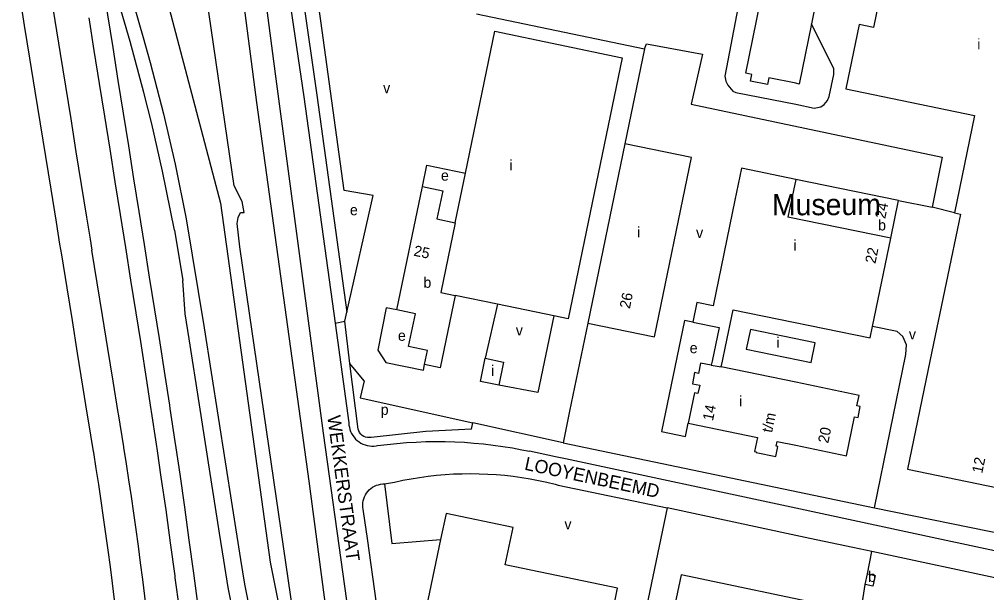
# Model space of a CAD drawing. Extents: x 157699 to 159683, y 381451 to 383293.
# Drawn here: x 157757.7 to 158121.9, y 382412.9 to 382628.7 of the extents above; entities that cross this region are included whole.
import ezdxf

# ---------------------------------------------------------------- set-up
doc = ezdxf.new("R2010")
doc.units = 0
for name, color, linetype in [('BLT_Basislijn', 7, 'Continuous'), ('BLT_Bebouwing', 7, 'Continuous'), ('BLT_Bebouwing_beschrifting', 7, 'Continuous'), ('BLT_Centroide', 7, 'Continuous'), ('BLT_Huisnummer', 7, 'Continuous'), ('BLT_Huisnummer_reeks', 7, 'Continuous'), ('BLT_Onderdoorgang_en_onderverdeling', 7, 'Continuous'), ('BLT_Onderverdeling_panden', 7, 'Continuous'), ('BLT_Straatnaam', 7, 'Continuous'), ('BLT_Vlakafsluiter', 7, 'Continuous')]:
    doc.layers.add(name, color=color, linetype=linetype)

msp = doc.modelspace()

# ---------------------------------------------------------------- linework, layer by layer
at = {"layer": 'BLT_Basislijn'}
for p, q in [((157845.48, 382672.76), (157853.96, 382608.2)), ((157840.85, 382644.96), (157847.02, 382597.39)), ((157857.82, 382647.47), (157864.76, 382599.52)), ((157863.31, 382644.46), (157869.71, 382600.22)), ((157871.21, 382628.11), (157869.03, 382643.28)), ((157929.77, 382630.74), (157993.12, 382617.66)), ((157993.12, 382617.66), (157985.72, 382581.9)), ((157853.96, 382608.2), (157872.09, 382472.97)), ((157847.02, 382597.39), (157866.68, 382454.83)), ((157864.76, 382599.52), (157876.54, 382514.37)), ((157869.71, 382600.22), (157881.02, 382518.43)), ((158088.7, 382560.53), (158101.42, 382557.97)), ((157937.68, 382521.51), (157933.14, 382501.1)), ((157876.54, 382514.37), (157881.73, 382476.82)), ((157882.18, 382499.13), (157880.28, 382515.11)), ((157971.78, 382514.34), (157964.88, 382481.2)), ((157885.29, 382474.45), (157882.18, 382499.13)), ((157887.46, 382492.69), (157882.18, 382499.13)), ((157887.46, 382492.69), (157886.04, 382486.18)), ((157886.04, 382486.18), (157928.38, 382476.87)), ((157964.88, 382481.2), (157962.41, 382469.24)), ((157927.92, 382474.42), (157928.38, 382476.87)), ((157962.41, 382469.24), (157928.38, 382476.87)), ((157910.79, 382473.51), (157890.1, 382471.35)), ((157927.92, 382474.42), (157910.79, 382473.51)), ((157872.09, 382472.97), (157882.28, 382400.27)), ((157959.59, 382464), (157949.82, 382466.12)), ((157962.41, 382469.24), (158079.72, 382444.87)), ((157963.3, 382463.21), (157959.59, 382464)), ((158050, 382444.69), (157963.3, 382463.21)), ((157866.68, 382454.83), (157876.58, 382380.56)), ((157960.62, 382453.39), (158001.58, 382444.81)), ((158001.58, 382444.81), (157980.31, 382343.07)), ((158050, 382434.46), (158001.58, 382444.81)), ((158079.72, 382444.87), (158141.73, 382432.11)), ((158078.71, 382428.33), (158071.51, 382429.87)), ((158167.06, 382409.46), (158078.71, 382428.33)), ((158072.5, 382391.84), (158076.17, 382415.97))]:
    msp.add_line(p, q, dxfattribs=at)
for points in [[(158050, 382728.84), (158049.04, 382728.04), (158047.57, 382725.13), (158047.35, 382722.9), (158028.29, 382633.59), (158023.36, 382607.28), (158023.67, 382605.44), (158024.49, 382603.94), (158026.38, 382601.73), (158027.5, 382601.2), (158050, 382596.73)], [(157814.31, 382688.66), (157806.99, 382684.84), (157802.17, 382680.96), (157802.03, 382678.58), (157833.39, 382559.57), (157852.12, 382424.4), (157856.21, 382403.71), (157863.37, 382370.92), (157866.2, 382371.54)], [(157866.2, 382371.54), (157863.56, 382386.33), (157840.74, 382543.08), (157839.7, 382551.81), (157840.08, 382554.13), (157840.98, 382555.96), (157842.28, 382555.94), (157841.59, 382560.09), (157838.61, 382565.98), (157821.37, 382684.05), (157819.38, 382686.74), (157815.85, 382688.1), (157814.31, 382688.66)], [(157786.93, 382685.77), (157790.71, 382670.14), (157793.44, 382659.75), (157795.78, 382651.33), (157798.88, 382640.71), (157804.35, 382621.87), (157806.97, 382612.47), (157811.94, 382593.14), (157816.3, 382574.16), (157820.46, 382553.59), (157827.25, 382512.59), (157837.82, 382445.33), (157840.91, 382425.36), (157842.49, 382416.11), (157844.46, 382406.06)], [(157814.33, 382483.41), (157812.61, 382494.6), (157810.67, 382506.97), (157810.41, 382508.58), (157808.7, 382519.32), (157806.73, 382531.66), (157804.76, 382544), (157802.79, 382556.35), (157800.82, 382568.69), (157798.85, 382581.04), (157796.88, 382593.38), (157794.91, 382605.72), (157792.94, 382618.07), (157790.97, 382630.41), (157789.01, 382642.76), (157787.04, 382655.1), (157785.07, 382667.44), (157783.19, 382679.23)], [(157816.09, 382549.38), (157811.54, 382571.58), (157807.5, 382589.41), (157804.61, 382601.15), (157799.45, 382620.43), (157793.85, 382639.38), (157788.43, 382658.53), (157783.19, 382679.23)], [(157769.02, 382640.59), (157771.02, 382628.25), (157773.02, 382615.91), (157775.01, 382603.57), (157777.01, 382591.23), (157779, 382578.89), (157781, 382566.55), (157782.99, 382554.21), (157784.34, 382545.91), (157784.99, 382541.86)], [(157773.64, 382540.03), (157772.98, 382544.08), (157771.64, 382552.38), (157769.65, 382564.72), (157767.65, 382577.06), (157765.65, 382589.39), (157763.66, 382601.73), (157761.66, 382614.07), (157759.67, 382626.41), (157757.67, 382638.75)], [(157783.82, 382629.27), (157785.78, 382616.93), (157787.75, 382604.58), (157789.72, 382592.24), (157791.69, 382579.89), (157793.66, 382567.55), (157795.63, 382555.21), (157797.6, 382542.86), (157799.57, 382530.52), (157801.54, 382518.17), (157803.25, 382507.43), (157803.51, 382505.83), (157805.45, 382493.48), (157807.23, 382481.85)], [(157881.02, 382518.43), (157890.85, 382562.4), (157879.97, 382564.3), (157871.21, 382628.11)], [(158050, 382596.73), (158057.02, 382595.33), (158059.48, 382595.73), (158060.72, 382596.71), (158062.02, 382598.21), (158062.66, 382599.64), (158064.32, 382607.98), (158064.41, 382610.05), (158055.97, 382627.04)], [(157993.12, 382617.66), (157993.86, 382619.55), (158014.87, 382615.64), (158010.69, 382596.77), (158105.22, 382576.88), (158101.42, 382557.97)], [(157909.45, 382565.74), (157911.12, 382573.78), (157925.67, 382570.76)], [(157816.09, 382549.38), (157819.24, 382530.36)], [(157783.39, 382479.71), (157781.62, 382490.68), (157779.62, 382503.02), (157777.63, 382515.36), (157775.63, 382527.7), (157773.64, 382540.03)], [(157794.88, 382480.74), (157792.97, 382492.51), (157790.98, 382504.85), (157788.98, 382517.19), (157786.99, 382529.53), (157784.99, 382541.86)], [(157834.63, 382425.07), (157833.05, 382435.28), (157831.55, 382444.89), (157829.52, 382457.76), (157825.51, 382483.63), (157821.65, 382508.39), (157820.12, 382517.81), (157819.24, 382530.36)], [(157880.28, 382515.11), (157881.02, 382518.43)], [(157899.8, 382519.31), (157895.77, 382520.11), (157892.6, 382504.17), (157895.72, 382499.51), (157909.83, 382496.7), (157910.24, 382498.74)], [(157958.95, 382517.12), (157952.94, 382488.2), (157938.26, 382490.99)], [(157876.54, 382514.37), (157880.28, 382515.11)], [(158011.23, 382514.71), (158008.13, 382515.35), (157999.5, 382473.51), (158008.52, 382471.65), (158009.56, 382476.68)], [(158079.72, 382444.87), (158091.52, 382502.56), (158091.73, 382506.24), (158090.37, 382509.27), (158088.2, 382511.15), (158078.98, 382513.14)], [(157812.29, 382340.11), (157812.02, 382342.87), (157810.8, 382355.31), (157809.58, 382367.75), (157808.42, 382379.65), (157808.36, 382380.2), (157807.73, 382386.48), (157807.07, 382392.76), (157806.38, 382399.03), (157805.66, 382405.31), (157804.92, 382411.58), (157804.15, 382417.84), (157803.35, 382424.11), (157802.52, 382430.37), (157801.66, 382436.62), (157800.78, 382442.87), (157799.87, 382449.12), (157798.93, 382455.36), (157797.99, 382461.42), (157797.02, 382467.47), (157796.96, 382467.83), (157794.97, 382480.17), (157794.88, 382480.74)], [(157807.23, 382481.85), (157807.34, 382481.13), (157809.2, 382468.77), (157809.56, 382466.31), (157811.01, 382456.4), (157812.77, 382444.03), (157814.49, 382431.65), (157816.17, 382419.26), (157816.28, 382418.45), (157817.8, 382406.87), (157819.39, 382394.48), (157820.93, 382382.07), (157822.33, 382370.51), (157822.43, 382369.67), (157823.88, 382357.25), (157825.29, 382344.83), (157826.66, 382332.41), (157827.23, 382327.06)], [(157823.35, 382420.22), (157821.67, 382432.64), (157819.95, 382445.04), (157818.18, 382457.44), (157816.73, 382467.36), (157816.37, 382469.83), (157814.51, 382482.22), (157814.33, 382483.41)], [(157799.65, 382351.16), (157799.36, 382354.19), (157798.14, 382366.63), (157796.97, 382378.53), (157796.92, 382379.07), (157796.29, 382385.3), (157795.64, 382391.53), (157794.95, 382397.75), (157794.24, 382403.98), (157793.5, 382410.2), (157792.74, 382416.41), (157791.94, 382422.62), (157791.12, 382428.83), (157790.27, 382435.04), (157789.4, 382441.24), (157788.49, 382447.43), (157787.56, 382453.63), (157786.63, 382459.63), (157785.67, 382465.64), (157785.61, 382466), (157783.62, 382478.34), (157783.39, 382479.71)], [(157881.73, 382476.82), (157881.79, 382475.98), (157881.93, 382475.14), (157882.14, 382474.32), (157882.43, 382473.53), (157882.8, 382472.77), (157883.24, 382472.04), (157883.74, 382471.36), (157884.3, 382470.73), (157884.92, 382470.15), (157885.6, 382469.64), (157886.32, 382469.19), (157887.07, 382468.81), (157887.86, 382468.51), (157888.68, 382468.28), (157889.51, 382468.13), (157890.35, 382468.05), (157891.2, 382468.06), (157892.04, 382468.15), (157892.53, 382468.24)], [(157890.1, 382471.35), (157889.45, 382471.25), (157888.76, 382471.27), (157888.05, 382471.42), (157887.36, 382471.7), (157886.74, 382472.1), (157886.2, 382472.61), (157885.77, 382473.2), (157885.47, 382473.82), (157885.29, 382474.45)], [(157892.53, 382468.24), (157896.15, 382468.7), (157899.77, 382469.07), (157903.4, 382469.37), (157907.04, 382469.59), (157910.68, 382469.73), (157914.32, 382469.78), (157917.96, 382469.76), (157921.6, 382469.66), (157925.24, 382469.48), (157928.87, 382469.22), (157932.5, 382468.87), (157936.12, 382468.45), (157939.72, 382467.95), (157943.32, 382467.37), (157946.9, 382466.71), (157949.82, 382466.12)], [(157895.12, 382453.8), (157898.94, 382454.52), (157902.08, 382455.19), (157905.24, 382455.79), (157908.41, 382456.3), (157911.6, 382456.73), (157914.79, 382457.09), (157917.99, 382457.36), (157921.2, 382457.56), (157924.41, 382457.68), (157927.62, 382457.71), (157930.84, 382457.67), (157934.05, 382457.55), (157937.26, 382457.34), (157940.46, 382457.06), (157943.65, 382456.7), (157946.84, 382456.25), (157950.01, 382455.73), (157953.17, 382455.13), (157956.31, 382454.45), (157959.43, 382453.7), (157960.62, 382453.39)], [(157887.31, 382443.49), (157887.12, 382444.27), (157887.01, 382445.06), (157886.98, 382445.86), (157887.02, 382446.66), (157887.15, 382447.45), (157887.35, 382448.22), (157887.63, 382448.97), (157887.99, 382449.69), (157888.41, 382450.37), (157888.9, 382451.01), (157889.45, 382451.59), (157890.06, 382452.11), (157890.71, 382452.57), (157891.41, 382452.97), (157892.15, 382453.29), (157892.91, 382453.54), (157893.69, 382453.71), (157894.49, 382453.8), (157895.12, 382453.8)], [(157895.12, 382453.8), (157897.98, 382431.45), (157916.28, 382432.84)], [(158194.81, 382413.76), (158103.17, 382433.33), (158050, 382444.69)], [(157898.92, 382360.23), (157888.73, 382433.33), (157887.31, 382443.49)], [(158071.51, 382429.87), (158055.29, 382433.33), (158050, 382434.46)], [(158077, 382419.97), (158078.71, 382428.33)], [(157859.77, 382288.75), (157860.35, 382288.55), (157861.15, 382288.53), (157861.96, 382288.73), (157862.91, 382289.57), (157863.78, 382290.94), (157864.3, 382292.34), (157864.51, 382294.07), (157864.52, 382296.33), (157864.35, 382298.77), (157862.1, 382313.28), (157859.69, 382326.35), (157857.03, 382338.03), (157854.64, 382347.07), (157851.82, 382356.67), (157848.72, 382366.03), (157845.72, 382375.52), (157842.98, 382385.26), (157840.24, 382396.11), (157838.14, 382405.55), (157836.33, 382414.77), (157834.63, 382425.07)], [(157835.26, 382320.03), (157835.19, 382320.74), (157833.87, 382333.19), (157832.5, 382345.64), (157831.09, 382358.08), (157829.63, 382370.52), (157829.53, 382371.37), (157828.13, 382382.96), (157826.58, 382395.38), (157824.99, 382407.81), (157823.35, 382420.22)]]:
    msp.add_lwpolyline(points, dxfattribs=at)
at = {"layer": 'BLT_Bebouwing'}
for p, q in [((158074.01, 382715.81), (158055.97, 382627.04)), ((157925.67, 382570.76), (157936.76, 382624.2)), ((157936.76, 382624.2), (157984.71, 382614.22)), ((157984.71, 382614.22), (157964.3, 382516.02)), ((157985.72, 382581.9), (157971.78, 382514.34)), ((157921.8, 382552.13), (157925.67, 382570.76)), ((157906.87, 382517.9), (157899.8, 382519.31)), ((157982.96, 382414.52), (157940.64, 382423.37)), ((158076.17, 382415.97), (158077, 382419.97)), ((157969.59, 382350.49), (157982.96, 382414.52))]:
    msp.add_line(p, q, dxfattribs=at)
for points in [[(158065.05, 382744.09), (158064.03, 382739.16), (158082.51, 382735.35), (158081.7, 382731.53), (158092.94, 382729.21), (158093.74, 382733.06), (158097.94, 382732.2), (158096.75, 382726.32), (158099.84, 382725.66), (158086.48, 382660.51), (158082.67, 382661.26), (158081.31, 382654.6), (158085.1, 382653.82), (158079.31, 382625.67), (158073.93, 382626.78), (158068.95, 382602.56), (158117.29, 382592.52), (158109.76, 382555.86)], [(158050, 382604.65), (158039.95, 382606.69), (158039.43, 382604.18), (158033.02, 382605.5), (158033.54, 382607.99), (158031.21, 382608.47), (158050, 382700.92)], [(158055.97, 382627.04), (158051.36, 382604.37), (158050, 382604.65)], [(157971.78, 382514.34), (157996.88, 382509.24), (158010.79, 382576.72), (157985.72, 382581.9)], [(158050, 382568.47), (158029.6, 382572.65), (158027.15, 382560.7)], [(158088.7, 382560.53), (158050, 382568.47)], [(157899.8, 382519.31), (157909.45, 382565.74)], [(157909.45, 382565.74), (157917.13, 382564.14)], [(157917.13, 382564.14), (157914.93, 382553.56), (157921.8, 382552.13)], [(158027.15, 382560.7), (158018.98, 382520.88), (158012.76, 382522.16), (158011.23, 382514.71)], [(158085.79, 382546.33), (158088.7, 382560.53)], [(158109.76, 382555.86), (158112.01, 382555.39), (158101.33, 382503.64)], [(158078.98, 382513.14), (158085.79, 382546.33)], [(157921.78, 382524.79), (157916.14, 382497.52), (157910.24, 382498.74)], [(157937.68, 382521.51), (157921.78, 382524.79)], [(157958.95, 382517.12), (157937.68, 382521.51)], [(157910.24, 382498.74), (157911.34, 382504.02), (157904.27, 382505.5), (157906.87, 382517.9)], [(157964.3, 382516.02), (157958.95, 382517.12)], [(158023.6, 382505.59), (158026.43, 382519.38), (158078.1, 382508.84), (158078.98, 382513.14)], [(158011.23, 382514.71), (158021.16, 382512.66), (158018.57, 382500), (158018.24, 382498.51)], [(158021.97, 382497.84), (158022.45, 382500.01), (158023.6, 382505.59)], [(158101.33, 382503.64), (158092.15, 382459.38)], [(157938.26, 382490.99), (157931.36, 382492.4), (157933.14, 382501.1)], [(157933.14, 382501.1), (157940.03, 382499.69), (157938.26, 382490.99)], [(158018.24, 382498.51), (158014.22, 382499.34), (158013.42, 382495.43), (158011.95, 382495.74), (158011.09, 382491.51), (158013.86, 382490.94), (158013.22, 382487.81), (158011.91, 382488.08), (158009.56, 382476.68)], [(158050, 382492.09), (158021.97, 382497.84)], [(158092.15, 382459.38), (158137.1, 382450.14), (158146.31, 382495.33)], [(158073.85, 382487.14), (158050, 382492.09)], [(158050, 382468.35), (158069.18, 382464.4), (158072.21, 382479.12), (158073.47, 382478.86), (158074.32, 382482.98), (158073.05, 382483.24), (158073.85, 382487.14)], [(158009.56, 382476.68), (158035.68, 382471.3), (158034.54, 382466.01), (158035.17, 382465.88), (158035.13, 382465.68), (158042.51, 382464.18), (158043.26, 382467.91), (158042.66, 382468.03), (158043.02, 382469.79), (158050, 382468.35)], [(157940.64, 382423.37), (157943.59, 382437.46), (157918.35, 382442.73), (157916.28, 382432.84)], [(157916.28, 382432.84), (157909.75, 382401.65), (157923.82, 382398.69)], [(158064.19, 382407.61), (158006.84, 382419.65), (157988.31, 382331.62), (157933.9, 382343.05)], [(158077, 382419.97), (158079.95, 382419.39), (158079.1, 382415.38), (158076.17, 382415.97)]]:
    msp.add_lwpolyline(points, dxfattribs=at)
msp.add_lwpolyline([(158032.94, 382511.99), (158031.4, 382504.51), (158055.8, 382499.51), (158057.34, 382506.99)], close=True, dxfattribs=at)
at = {"layer": 'BLT_Onderdoorgang_en_onderverdeling'}
for p in [(158050, 382568.47), (158085.79, 382546.33)]:
    msp.add_line(p, (158047.09, 382554.27), dxfattribs=at)
at = {"layer": 'BLT_Onderverdeling_panden'}
msp.add_line((158018.24, 382498.51), (158021.97, 382497.84), dxfattribs=at)
msp.add_lwpolyline([(157921.8, 382552.13), (157916.36, 382525.92), (157921.78, 382524.79)], dxfattribs=at)
at = {"layer": 'BLT_Vlakafsluiter'}
msp.add_line((158109.76, 382555.86), (158101.42, 382557.97), dxfattribs=at)

# ---------------------------------------------------------------- texts
at = {"layer": 'BLT_Bebouwing_beschrifting'}
msp.add_text('Museum', height=8, rotation=0.1745, dxfattribs=at).set_placement((158041.08, 382554.92))
at = {"layer": 'BLT_Centroide'}
for s, p in [('i', (158118.39, 382617.41)), ('v', (157894.65, 382600.89)), ('i', (157942.25, 382571.81)), ('e', (157916.43, 382567.97)), ('e', (157882.15, 382554.97)), ('b', (158081.04, 382549.25)), ('i', (157990.26, 382546.61)), ('v', (158012.5, 382546.42)), ('i', (158049.12, 382541.69)), ('b', (157909.82, 382527.67)), ('e', (157900.22, 382507.7)), ('v', (157944.62, 382509.71)), ('v', (158092.63, 382508.21)), ('e', (158010.09, 382503.02)), ('i', (158042.73, 382505.06)), ('i', (157935.34, 382494.51)), ('i', (158028.68, 382482.97)), ('p', (157893.73, 382479.82)), ('v', (157962.93, 382436.7)), ('b', (158077.25, 382416.95))]:
    msp.add_text(s, height=4, dxfattribs=at).set_placement(p)
at = {"layer": 'BLT_Huisnummer'}
for s, rotation, p in [('24', 78.4049, (158083.71, 382553.46)), ('25', 348.2588, (157905.93, 382539.78)), ('22', 78.4049, (158080.01, 382536.56)), ('26', 78.4031, (157987.55, 382519.57))]:
    msp.add_text(s, height=4, rotation=rotation, dxfattribs=at).set_placement(p)
at = {"layer": 'BLT_Huisnummer_reeks'}
for s, rotation, p in [('14', 78.3657, (158018.83, 382477.34)), ('t/m', 78.4049, (158041.1, 382472.91)), ('20', 78.3657, (158062.25, 382468.89)), ('12', 78.2853, (158120.24, 382457.58))]:
    msp.add_text(s, height=4, rotation=rotation, dxfattribs=at).set_placement(p)
at = {"layer": 'BLT_Straatnaam'}
for s, height, rotation, p in [('WEKKERSTRAAT', 5, 277.6491, (157873.61, 382479.28)), ('LOOYENBEEMD', 4.9999, 347.9979, (157947.61, 382459.2))]:
    msp.add_text(s, height=height, rotation=rotation, dxfattribs=at).set_placement(p)

doc.saveas('drawing.dxf')
